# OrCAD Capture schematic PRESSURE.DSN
size A; company: mycompany; note: line1; note: line 2
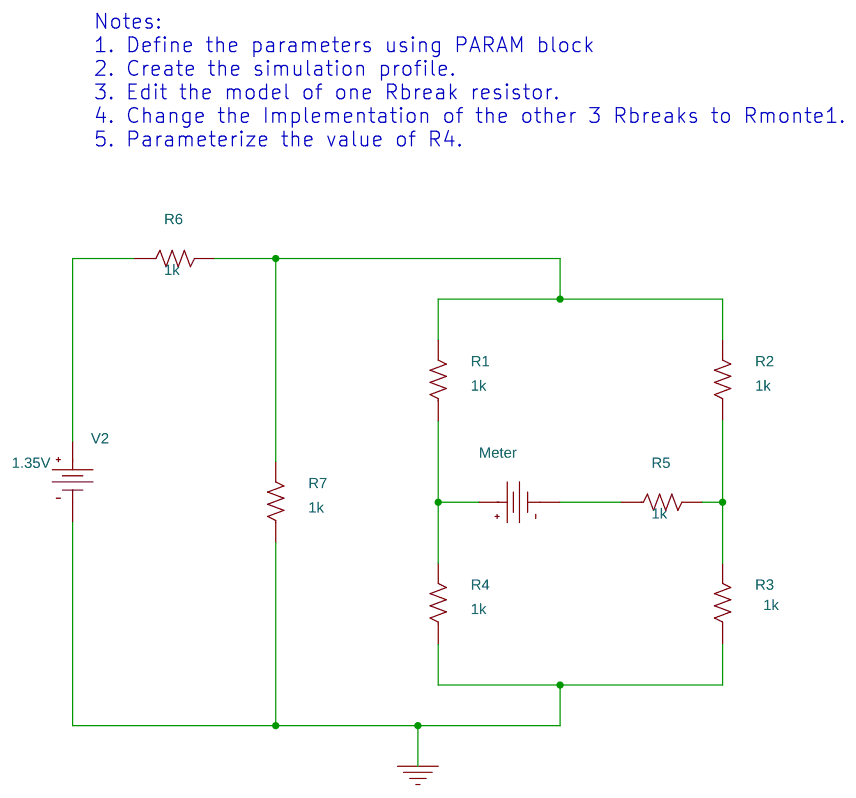
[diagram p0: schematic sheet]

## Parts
Meter  VDC
R1  1k
R2  1k
R3  1k
R4  1k
R5  1k  [AX/RC05]
R6  1k  [AX/RC05]
R7  1k  [AX/RC05]
V2  VDC

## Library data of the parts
Meter = VDC
R1-R4 = Rbreak
R5-R7 = R
V2 = VDC: DC: 1.35V

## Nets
0: R3.1 R4.1 R7.1 V2.1(-)
N00190: Meter.0(+) R1.1 R4.0(2)
N00204: Meter.1(-) R5.1
N00212: R1.0(2) R2.0(2) R6.2 R7.2
N00236: R2.1 R3.0(2) R5.2
N00540: R6.1 V2.0(+)

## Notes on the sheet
- Notes:
  1. Define the parameters using PARAM block
  2. Create the simulation profile.
  3. Edit the model of one Rbreak resistor.
  4. Change the Implementation of the other 3 Rbreaks to Rmonte1.
  5. Parameterize the value of R4.
